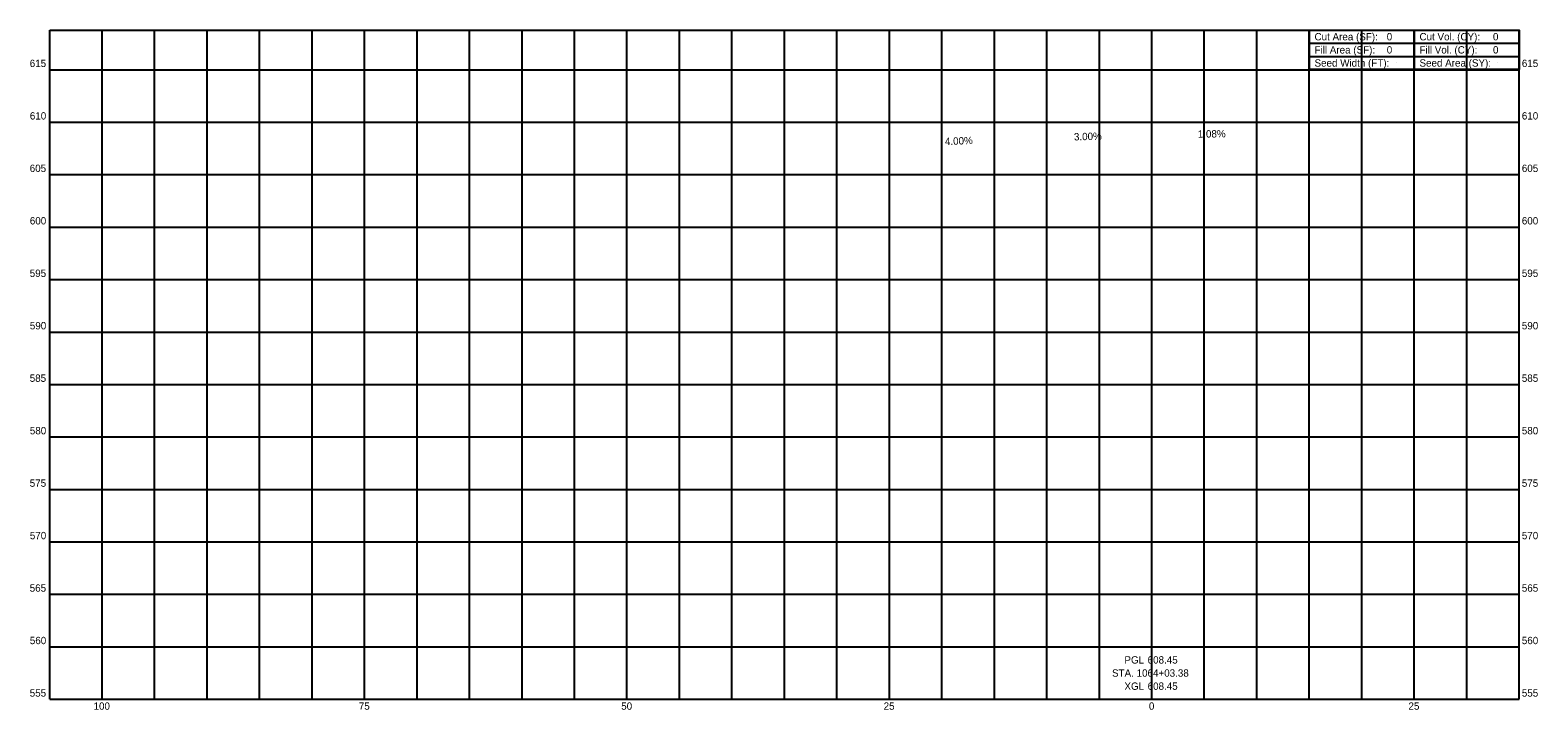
# Model space of a CAD drawing. Extents: x -107 to 37, y 554 to 619.
import ezdxf

# ---------------------------------------------------------------- set-up
doc = ezdxf.new("R2010")
doc.units = 0
for name, color, linetype in [('Default', 7, 'Continuous'), ('SH_Data', 7, 'Continuous'), ('SH_Major_Grid_Line', 7, 'Continuous'), ('SH_Masking', 7, 'Continuous'), ('SH_Text', 7, 'Continuous')]:
    doc.layers.add(name, color=color, linetype=linetype)

msp = doc.modelspace()

# ---------------------------------------------------------------- linework, layer by layer
at = {"layer": 'Default'}
msp.add_circle((35, 618.77), 0.000417, dxfattribs=at)
msp.add_circle((35, 618.77), 0.000417, dxfattribs=at)
msp.add_circle((35, 618.77), 0.000417, dxfattribs=at)
msp.add_circle((35, 618.77), 0.000417, dxfattribs=at)
msp.add_circle((35, 618.77), 0.000417, dxfattribs=at)
msp.add_circle((35, 618.77), 0.000417, dxfattribs=at)
msp.add_circle((35, 618.77), 0.000417, dxfattribs=at)
msp.add_circle((35, 618.77), 0.000417, dxfattribs=at)
msp.add_circle((35, 618.77), 0.000417, dxfattribs=at)
msp.add_circle((35, 618.77), 0.000417, dxfattribs=at)
msp.add_circle((35, 618.77), 0.000417, dxfattribs=at)
msp.add_circle((35, 618.77), 0.000417, dxfattribs=at)
at = {"layer": 'SH_Data'}
for p, q in [((15, 618.77), (35, 618.77)), ((15, 618.77), (15, 616.27)), ((25, 618.77), (25, 615.02)), ((35, 618.77), (35, 616.27)), ((15, 617.52), (35, 617.52)), ((15, 616.27), (35, 616.27)), ((23.3, 615.64), (23.3, 615.64)), ((32.95, 615.64), (32.95, 615.64))]:
    msp.add_line(p, q, dxfattribs=at)
msp.add_lwpolyline([(15, 616.27), (15, 615.02), (35, 615.02), (35, 616.27)], dxfattribs=at)
at = {"layer": 'SH_Major_Grid_Line'}
for p, q in [((-105, 618.77), (35, 618.77)), ((-105, 555), (-105, 618.77)), ((-100, 555), (-100, 618.77)), ((-95, 555), (-95, 618.77)), ((-90, 555), (-90, 618.77)), ((-85, 555), (-85, 618.77)), ((-80, 555), (-80, 618.77)), ((-75, 555), (-75, 618.77)), ((-70, 555), (-70, 618.77)), ((-65, 555), (-65, 618.77)), ((-60, 555), (-60, 618.77)), ((-55, 555), (-55, 618.77)), ((-50, 555), (-50, 618.77)), ((-45, 555), (-45, 618.77)), ((-40, 555), (-40, 618.77)), ((-35, 555), (-35, 618.77)), ((-30, 555), (-30, 618.77)), ((-25, 555), (-25, 618.77)), ((-20, 555), (-20, 618.77)), ((-15, 555), (-15, 618.77)), ((-10, 555), (-10, 618.77)), ((-5, 555), (-5, 618.77)), ((0, 555), (0, 618.77)), ((5, 555), (5, 618.77)), ((10, 555), (10, 618.77)), ((15, 555), (15, 618.77)), ((20, 555), (20, 618.77)), ((25, 555), (25, 618.77)), ((30, 555), (30, 618.77)), ((35, 555), (35, 618.77)), ((-105, 615), (35, 615)), ((-105, 610), (35, 610)), ((-105, 605), (35, 605)), ((-105, 600), (35, 600)), ((-105, 595), (35, 595)), ((-105, 590), (35, 590)), ((-105, 585), (35, 585)), ((-105, 580), (35, 580)), ((-105, 575), (35, 575)), ((-105, 570), (35, 570)), ((-105, 565), (35, 565)), ((-105, 560), (35, 560)), ((-105, 555), (35, 555))]:
    msp.add_line(p, q, dxfattribs=at)
at = {"layer": 'SH_Masking'}
msp.add_lwpolyline([(15, 618.77), (35, 618.77), (35, 615.02), (15, 615.02)], close=True, dxfattribs=at)

# ---------------------------------------------------------------- texts
at = {"layer": 'SH_Text'}
for s, p in [('Cut Area (SF):', (15.5, 617.79)), ('0', (22.38, 617.79)), ('Cut Vol. (CY):', (25.5, 617.79)), ('0', (32.5, 617.79)), ('Fill Area (SF):', (15.5, 616.54)), ('0', (22.38, 616.54)), ('Fill Vol. (CY):', (25.5, 616.54)), ('0', (32.5, 616.54)), ('615', (-106.9, 615.25)), ('Seed Width (FT):', (15.5, 615.29)), ('Seed Area (SY):', (25.5, 615.29)), ('615', (35.25, 615.25)), ('610', (-106.89, 610.25)), ('610', (35.25, 610.25)), ('605', (-106.9, 605.25)), ('605', (35.25, 605.25)), ('600', (-106.89, 600.25)), ('600', (35.25, 600.25)), ('595', (-106.9, 595.25)), ('595', (35.25, 595.25)), ('590', (-106.89, 590.25)), ('590', (35.25, 590.25)), ('585', (-106.9, 585.25)), ('585', (35.25, 585.25)), ('580', (-106.89, 580.25)), ('580', (35.25, 580.25)), ('575', (-106.9, 575.25)), ('575', (35.25, 575.25)), ('570', (-106.89, 570.25)), ('570', (35.25, 570.25)), ('565', (-106.9, 565.25)), ('565', (35.25, 565.25)), ('560', (-106.89, 560.25)), ('560', (35.25, 560.25)), ('PGL ', (-2.61, 558.4)), ('608.45', (-0.4, 558.4)), ('STA. 1064+03.38', (-3.79, 557.15)), ('555', (-106.9, 555.25)), ('XGL ', (-2.61, 555.9)), ('608.45', (-0.4, 555.9)), ('555', (35.25, 555.25)), ('100', (-100.82, 554)), ('75', (-75.55, 554)), ('50', (-50.55, 554)), ('25', (-25.55, 554)), ('0', (-0.28, 554)), ('25', (24.45, 554))]:
    msp.add_text(s, height=0.7, dxfattribs=at).set_placement(p)
for s, rotation, p in [('3.00%', 1.7199, (-7.41, 608.25)), ('1.08%', 0.6198, (4.38, 608.52)), ('4.00%', 2.2906, (-19.7, 607.81))]:
    msp.add_text(s, height=0.7, rotation=rotation, dxfattribs=at).set_placement(p)

doc.saveas('drawing.dxf')
